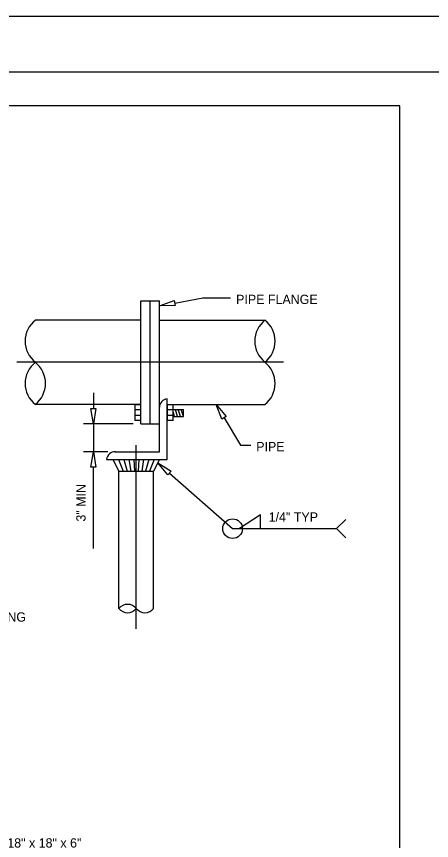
# Model space of a CAD drawing. Extents: x 2147138 to 2147698, y 2147153 to 2147515.
# Drawn here: x 2147502 to 2147555.6, y 2147408.7 to 2147515.1 of the extents above; entities that cross this region are included whole.
import ezdxf

# ---------------------------------------------------------------- set-up
doc = ezdxf.new("R2010")
doc.units = 0
for name, color, linetype in [('CONSTRUCTION_CLASS', 7, 'Continuous'), ('G-ANNO-TEXT-LW10', 7, 'Continuous'), ('G-DETL-CNTR', 7, 'Continuous'), ('G-DETL-LW10', 7, 'Continuous'), ('G-DETL-LW20', 7, 'Continuous'), ('G-DETL-PATT', 7, 'Continuous'), ('PATTERN_CLASS', 7, 'Continuous')]:
    doc.layers.add(name, color=color, linetype=linetype)

msp = doc.modelspace()

# ---------------------------------------------------------------- linework, layer by layer
at = {"layer": 'CONSTRUCTION_CLASS'}
for p, q in [((2147697.66, 2147515.08), (2147137.79, 2147515.08)), ((2147160.2, 2147507.94), (2147689.06, 2147507.94))]:
    msp.add_line(p, q, dxfattribs=at)
at = {"layer": 'G-ANNO-TEXT-LW10'}
for p, q in [((2147522.43, 2147478.07), (2147526.04, 2147478.74)), ((2147526.04, 2147478.74), (2147529.61, 2147478.74)), ((2147511.94, 2147466.46), (2147511.94, 2147464.46)), ((2147528.79, 2147463.25), (2147530.9, 2147459.72)), ((2147517.06, 2147462.46), (2147510.66, 2147462.46)), ((2147511.94, 2147462.46), (2147511.94, 2147458.85)), ((2147513.81, 2147458.85), (2147510.66, 2147458.85)), ((2147530.9, 2147459.72), (2147532.25, 2147459.72)), ((2147511.94, 2147446.36), (2147511.94, 2147456.85)), ((2147521.75, 2147456.11), (2147529.9, 2147448.93)), ((2147533.48, 2147450.72), (2147530.77, 2147448.93)), ((2147533.48, 2147448.93), (2147533.48, 2147450.72)), ((2147543.3, 2147448.93), (2147544.49, 2147450.12)), ((2147529.9, 2147448.93), (2147543.3, 2147448.93)), ((2147543.3, 2147448.93), (2147544.49, 2147447.74))]:
    msp.add_line(p, q, dxfattribs=at)
for points in [[(2147522.49, 2147477.74), (2147520.46, 2147477.7), (2147522.37, 2147478.39)], [(2147512.27, 2147464.46), (2147511.94, 2147462.46), (2147511.6, 2147464.46)], [(2147528.51, 2147463.07), (2147527.77, 2147464.96), (2147529.08, 2147463.42)], [(2147511.6, 2147456.85), (2147511.94, 2147458.85), (2147512.27, 2147456.85)], [(2147521.53, 2147455.86), (2147520.25, 2147457.44), (2147521.97, 2147456.36)]]:
    msp.add_lwpolyline(points, close=True, dxfattribs=at)
msp.add_circle((2147529.9, 2147448.93), 1.27, dxfattribs=at)
at = {"layer": 'G-DETL-CNTR'}
for p, q in [((2147536.47, 2147470.41), (2147502.05, 2147470.41)), ((2147517.46, 2147435.97), (2147517.46, 2147459.71))]:
    msp.add_line(p, q, dxfattribs=at)
at = {"layer": 'G-DETL-LW10'}
for p, q in [((2147518.06, 2147464.9), (2147517.29, 2147464.9)), ((2147517.29, 2147464.9), (2147517.29, 2147462.91)), ((2147518.06, 2147464.26), (2147517.29, 2147464.26)), ((2147518.06, 2147462.91), (2147518.06, 2147464.9)), ((2147522.23, 2147464.9), (2147521.46, 2147464.9)), ((2147521.46, 2147464.9), (2147521.46, 2147462.91)), ((2147522.23, 2147464.26), (2147521.46, 2147464.26)), ((2147522.23, 2147462.91), (2147522.23, 2147464.9)), ((2147522.23, 2147464.33), (2147523.57, 2147464.33)), ((2147522.8, 2147463.41), (2147522.51, 2147464.33)), ((2147523.18, 2147463.41), (2147522.89, 2147464.33)), ((2147523.57, 2147463.41), (2147523.28, 2147464.33)), ((2147523.57, 2147463.41), (2147523.57, 2147464.33)), ((2147518.06, 2147463.55), (2147517.29, 2147463.55)), ((2147522.23, 2147463.55), (2147521.46, 2147463.55)), ((2147522.41, 2147463.41), (2147522.23, 2147464.01)), ((2147522.23, 2147463.41), (2147523.57, 2147463.41)), ((2147518.06, 2147462.91), (2147517.29, 2147462.91)), ((2147522.23, 2147462.91), (2147521.46, 2147462.91))]:
    msp.add_line(p, q, dxfattribs=at)
at = {"layer": 'G-DETL-LW20'}
for p, q in [((2147518.06, 2147462.46), (2147518.06, 2147478.36)), ((2147518.06, 2147478.36), (2147520.46, 2147478.36)), ((2147519.26, 2147462.46), (2147519.26, 2147478.36)), ((2147520.46, 2147458.85), (2147520.46, 2147478.36)), ((2147518.06, 2147475.86), (2147504.45, 2147475.86)), ((2147520.46, 2147475.86), (2147534.07, 2147475.86)), ((2147521.46, 2147457.85), (2147521.46, 2147465.69)), ((2147518.06, 2147464.96), (2147504.45, 2147464.96)), ((2147521.46, 2147464.96), (2147534.07, 2147464.96)), ((2147518.06, 2147462.46), (2147520.46, 2147462.46)), ((2147514.69, 2147458.85), (2147520.46, 2147458.85)), ((2147513.62, 2147457.85), (2147521.46, 2147457.85)), ((2147514.44, 2147457.85), (2147515.21, 2147456.35)), ((2147515.19, 2147457.85), (2147515.77, 2147456.35)), ((2147515.88, 2147457.85), (2147516.29, 2147456.35)), ((2147516.53, 2147457.85), (2147516.77, 2147456.35)), ((2147517.16, 2147457.85), (2147517.25, 2147456.35)), ((2147517.79, 2147457.85), (2147517.71, 2147456.35)), ((2147518.42, 2147457.85), (2147518.18, 2147456.35)), ((2147519.07, 2147457.85), (2147518.67, 2147456.35)), ((2147519.76, 2147457.85), (2147519.19, 2147456.35)), ((2147520.46, 2147457.85), (2147519.71, 2147456.35)), ((2147515.21, 2147438.61), (2147515.21, 2147456.35)), ((2147515.21, 2147456.35), (2147519.71, 2147456.35)), ((2147519.71, 2147438.61), (2147519.71, 2147456.35))]:
    msp.add_line(p, q, dxfattribs=at)
for centre, radius, start, end in [((2147506.6, 2147473.14), 3.47, 128.3518, 231.6482), ((2147536.23, 2147473.14), 3.47, 128.3518, 231.6482), ((2147531.92, 2147473.14), 3.47, 308.3518, 51.6482), ((2147506.6, 2147467.69), 3.47, 128.3518, 231.6482), ((2147502.29, 2147467.69), 3.47, 308.3518, 51.6482), ((2147531.92, 2147467.69), 3.47, 308.3518, 51.6482), ((2147521.59, 2147464.56), 1.14, 96.7858, 177.028), ((2147514.75, 2147457.72), 1.14, 87.028, 173.2142), ((2147516.34, 2147437.72), 1.43, 38.3518, 141.6482), ((2147516.34, 2147439.5), 1.43, 218.3518, 321.6482), ((2147518.59, 2147439.5), 1.43, 218.3518, 321.6482)]:
    msp.add_arc(centre, radius, start, end, dxfattribs=at)
at = {"layer": 'G-DETL-PATT'}
for centre, radius, start, end in [((2147536.23, 2147473.14), 3.47, 128.3518, 231.6482), ((2147531.92, 2147473.14), 3.47, 308.3518, 51.6482), ((2147506.6, 2147467.69), 3.47, 128.3518, 231.6482), ((2147502.29, 2147467.69), 3.47, 308.3518, 51.6482), ((2147516.34, 2147437.72), 1.43, 38.3518, 141.6482), ((2147516.34, 2147439.5), 1.43, 218.3518, 321.6482)]:
    msp.add_arc(centre, radius, start, end, dxfattribs=at)
at = {"layer": 'PATTERN_CLASS'}
for p, q in [((2147551.49, 2147503.54), (2147427.3, 2147503.54)), ((2147551.49, 2147351.27), (2147551.49, 2147503.54))]:
    msp.add_line(p, q, dxfattribs=at)

# ---------------------------------------------------------------- texts
at = {"layer": 'G-ANNO-TEXT-LW10'}
for s, p in [('PIPE FLANGE', (2147530.35, 2147477.94)), ('PIPE', (2147532.95, 2147458.92)), ('1/4" TYP', (2147534.55, 2147449.83)), ('ANCHORS WITH LEVELING', (2147482.38, 2147436.92)), ('CONSTRUCT 18" x 18" x 6"', (2147490.31, 2147407.74))]:
    msp.add_text(s, height=1.2, dxfattribs=at).set_placement(p)
msp.add_text('3" MIN', height=1.2, rotation=90, dxfattribs=at).set_placement((2147510.93, 2147449.84))

doc.saveas('drawing.dxf')
